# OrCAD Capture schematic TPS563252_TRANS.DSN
size Custom
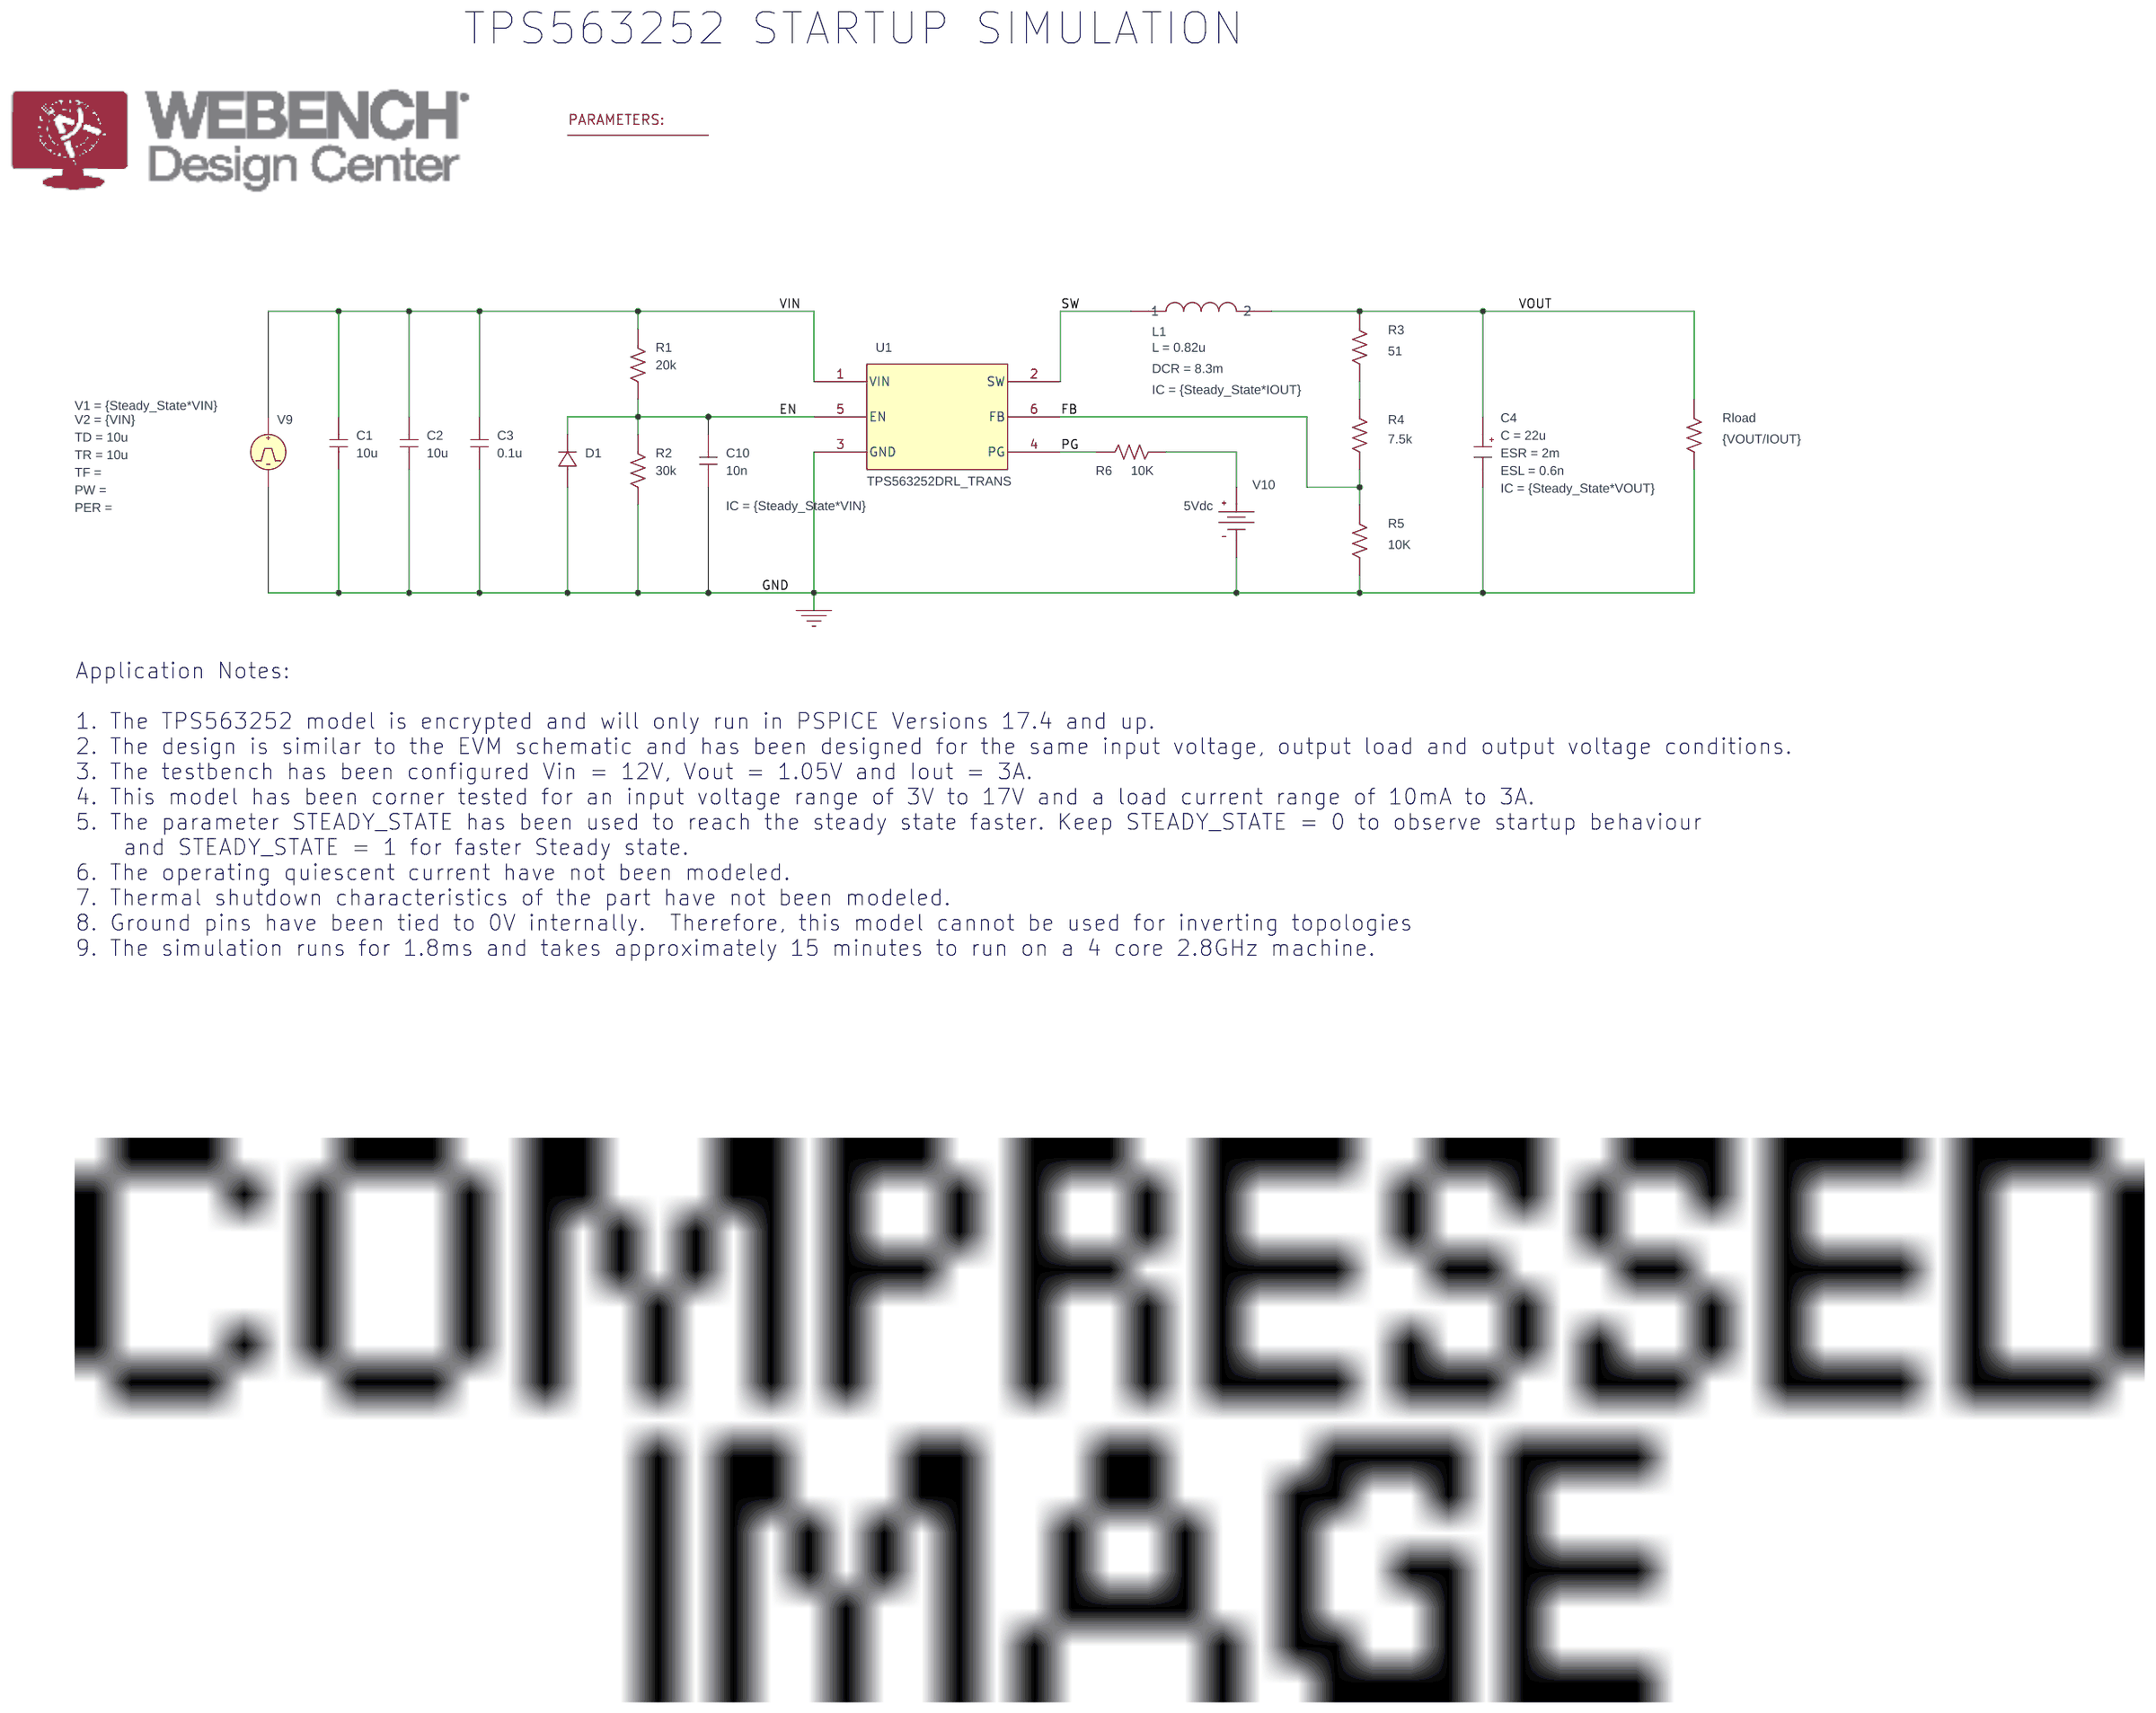
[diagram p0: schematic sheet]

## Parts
3  PARAM
C1  10u  [RAD/CK05]
C2  10u  [RAD/CK05]
C3  0.1u  [RAD/CK05]
C4  CESR
C10  10n  [RAD/CK05]
D1  Dbreak
L1  LDCR
R1  20k  [AX/RC05]
R2  30k  [AX/RC05]
R3  51  [AX/RC05]
R4  7.5k  [AX/RC05]
R5  10K  [AX/RC05]
R6  10K  [AX/RC05]
Rload  {VOUT/IOUT}  [AX/RC05]
U1  TPS563252DRL_TRANS
V9  VPULSE
V10  VDC

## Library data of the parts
3 = PARAM: Steady_State: 0; VIN: 12; VOUT: 1.05
C1-C3 = C
C4 = CESR_0: C: 22u; ESL: 0.6n; ESR: 2m; IC: {Steady_State*VOUT}
C10 = C: IC: {Steady_State*VIN}
D1 = Dbreak
L1 = LDCR: DCR: 8.3m; IC: {Steady_State*IOUT}; L: 0.82u
R1-R6 Rload = R
U1 = TPS563252_TRANS
V9 = VPULSE: TD: 10u; TR: 10u; V1: {Steady_State*VIN}; V2: {VIN}
V10 = VDC: DC: 5Vdc

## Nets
VIN: C1.1 C2.1 C3.1 R1.1 U1.1(VIN) V9.1(+)
0: C1.2 C2.2 C3.2 C4.2(OUT) C10.2 D1.0(1) R2.2 R5.2 Rload.2 U1.3(GND) V9.2(-) V10.1(-)
EN: C10.1 D1.1(2) R1.2 R2.1 U1.5(EN)
FB: R4.2 R5.1 U1.6(FB)
PG: R6.1 U1.4(PG)
SW: L1.1 U1.2(SW)
VOUT: C4.1(IN) L1.2 R3.1 Rload.1
N00824: R3.2 R4.1
N01130: R6.2 V10.0(+)

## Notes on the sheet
- TPS563252 STARTUP SIMULATION
- Application Notes:
  1. The TPS563252 model is encrypted and will only run in PSPICE Versions 17.4 and up.
  2. The design is similar to the EVM schematic and has been designed for the same input voltage, output load and output voltage conditions.
  3. The testbench has been configured Vin = 12V, Vout = 1.05V and Iout = 3A.
  4. This model has been corner tested for an input voltage range of 3V to 17V and a load current range of 10mA to 3A.
  5. The parameter STEADY_STATE has been used to reach the steady state faster. Keep STEADY_STATE = 0 to observe startup behaviour
      and STEADY_STATE = 1 for faster Steady state.
  6. The operating quiescent current have not been modeled.
  7. Thermal shutdown characteristics of the part have not been modeled.
  8. Ground pins have been tied to 0V internally.  Therefore, this model cannot be used for inverting topologies
  9. The simulation runs for 1.8ms and takes approximately 15 minutes to run on a 4 core 2.8GHz machine.
